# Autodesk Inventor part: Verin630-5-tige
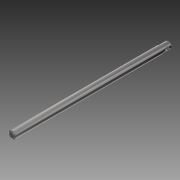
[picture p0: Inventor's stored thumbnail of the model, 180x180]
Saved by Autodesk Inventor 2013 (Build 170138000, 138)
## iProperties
Created: 2015-07
Part Number: Verin630-5-tige
Material: Générique
Document SubType Name: Modeling
Designer: OL
Density: 1 g/cm^3
Author: OL
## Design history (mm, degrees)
sketch "Esquisse1"
  geometry: L1 (0, 0)-(616, 0); L2 (0, 0)-(0, 10); L3 (3, 15)-(614.5, 15); L4 (616, 13.5)-(616, 0); L5 (3, 15)-(0, 10); L6 (614.5, 15)-(616, 13.5); L7 (616, 13.5)-(648, 13.5); L8 (648, 13.5)-(650, 11.5); L9 (650, 11.5)-(650, 0); L10 (616, 0)-(650, 0)
  constraints: 20 end point, 5 perpendicular, 2 parallel, 1 horizontal
  dimensions: "d0" = 616 distance of L1.start L1.end; "d1" = 15 distance between parallel lines of L1 L3; "d2" = 3 horizontal distance of L3.start L2.end; "d3" = 5 vertical distance of L3.start L2.end; "d4" = 1.5 horizontal distance of L3.end L4.start; "d5" = 1.5 horizontal distance of L3.end L4.start; "d6" = 34 distance between parallel lines of L4 L9; "d7" = 2 horizontal distance of L7.end L8.end
revolve "Révolution1" sketch "Esquisse1" stored, may be unused: angle "d8" = 90 deg
sketch "Esquisse2"
  geometry: L1 (650, -11.5)-(650, 11.5) reference; C1 r 8.1 at (632, 0); 1 further point
  constraints: 1 centre point
  dimensions: "d9" = 16.2 diameter of C1; "d11" = 18 distance from line of L1 C1.centre; "d12" = 0 vertical distance of C1.centre point (0, 0)
extrude "Extrusion1" cut sketch "Esquisse2" stored distance "d13" = 30; taper "d14" = 0 deg
sketch "Esquisse3"
  geometry: L1 (0, -10)-(0, 10) reference; C1 r 8.25 at (632, 0); 1 further point
  constraints: 1 centre point
  dimensions: "d15" = 632 distance from line of L1 C1.centre; "d16" = 16.5 diameter of C1
extrude "Extrusion2" cut sketch "Esquisse3" stored distance "d17" = 2; taper "d18" = 0 deg
node "Solide1"
